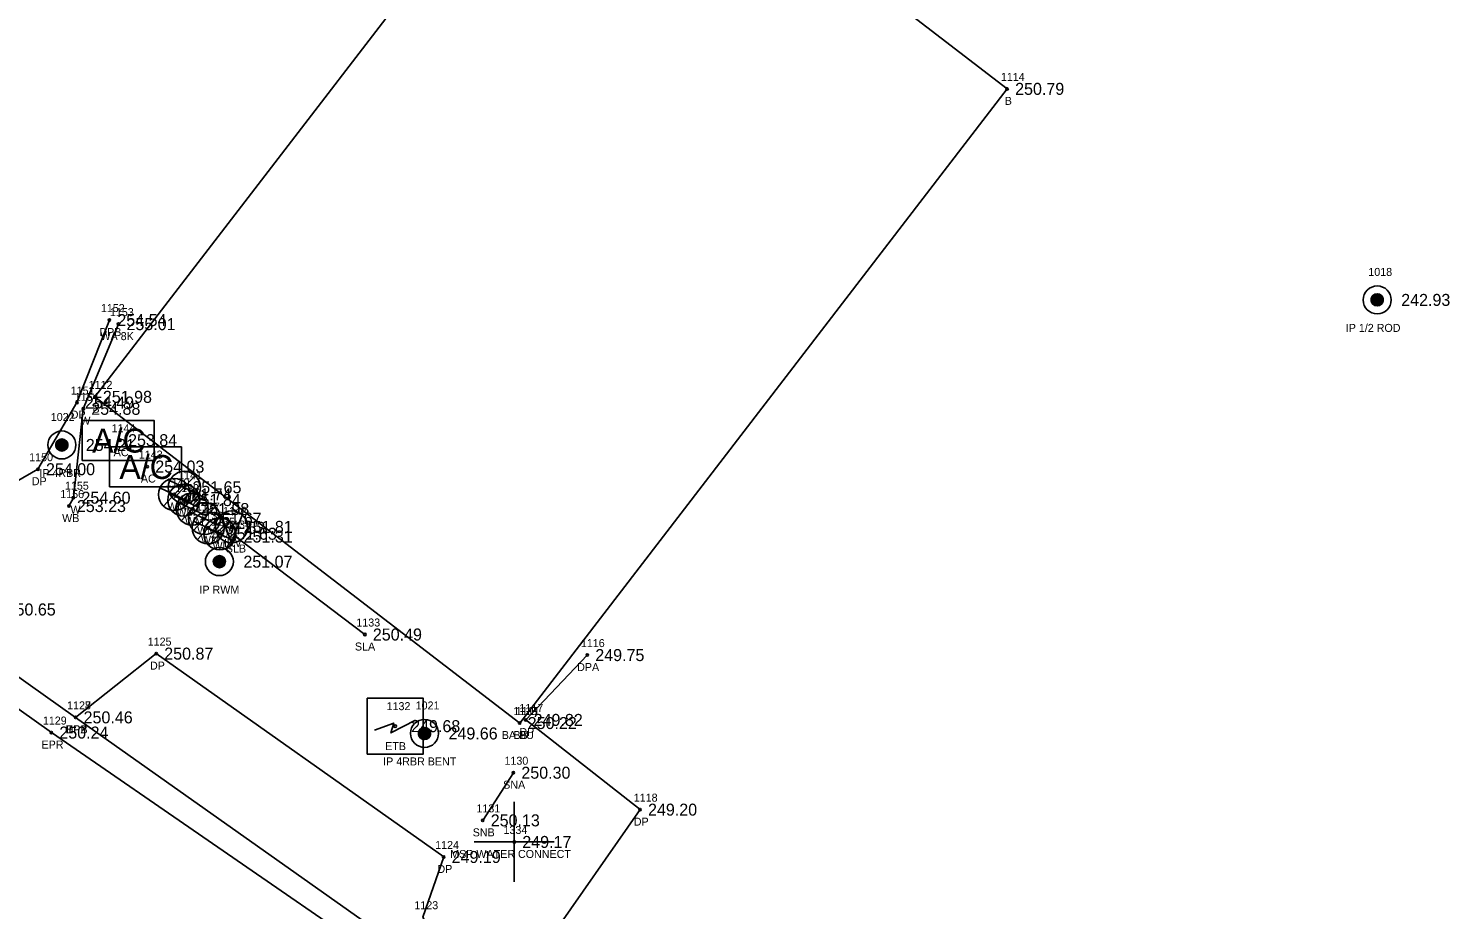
# Model space of a CAD drawing. Extents: x 1961231 to 1962574, y 799865 to 801120.
# Drawn here: x 1962101.5 to 1962279.1, y 800461.9 to 800572.1 of the extents above; entities that cross this region are included whole.
import ezdxf

# ---------------------------------------------------------------- set-up
doc = ezdxf.new("R2010")
doc.units = 0
for name, color, linetype in [('RD_EX_Bldg', 7, 'Continuous'), ('RD_EX_Bldg_txCode', 7, 'Continuous'), ('RD_EX_BldgApp', 7, 'Continuous'), ('RD_EX_BldgApp_txCode', 7, 'Continuous'), ('RD_EX_Driveway', 7, 'Continuous'), ('RD_EX_Driveway_txCode', 7, 'Continuous'), ('RD_EX_DV_Prop_txCode', 7, 'Continuous'), ('RD_EX_DV_PropPin', 7, 'Continuous'), ('RD_EX_Misc', 7, 'Continuous'), ('RD_EX_Misc_txCode', 7, 'Continuous'), ('RD_EX_Road', 7, 'Continuous'), ('RD_EX_Road_txCode', 7, 'Continuous'), ('RD_EX_TX_Bldg_ELEV', 7, 'Continuous'), ('RD_EX_TX_BldgApp_ELEV', 7, 'Continuous'), ('RD_EX_TX_Driveway_ELEV', 7, 'Continuous'), ('RD_EX_TX_DV_Prop_ELEV', 7, 'Continuous'), ('RD_EX_TX_Misc_ELEV', 7, 'Continuous'), ('RD_EX_TX_Road_ELEV', 7, 'Continuous'), ('RD_EX_TX_UT_ELEV', 7, 'Continuous'), ('RD_EX_TX_VEG_ELEV', 7, 'Continuous'), ('RD_EX_UT', 7, 'Continuous'), ('RD_EX_UT_txCode', 7, 'Continuous'), ('RD_EX_VEG', 7, 'Continuous'), ('RD_EX_VEG_txCode', 7, 'Continuous'), ('RD_SMD_Locator', 7, 'Continuous')]:
    doc.layers.add(name, color=color, linetype=linetype)

msp = doc.modelspace()

# ---------------------------------------------------------------- linework, layer by layer
at = {"layer": 'RD_EX_Bldg'}
msp.add_lwpolyline([(1962162.93, 800485.25), (1962109.84, 800526.04), (1962170.76, 800605.34), (1962223.85, 800564.55), (1962162.93, 800485.25)], dxfattribs=at)
at = {"layer": 'RD_EX_BldgApp'}
for p, q in [((1962126.93, 800507.79), (1962125.63, 800511.27)), ((1962126.93, 800507.79), (1962128.26, 800511.24)), ((1962162.14, 800479.04), (1962158.31, 800473.08))]:
    msp.add_line(p, q, dxfattribs=at)
msp.add_lwpolyline([(1962112.79, 800535.13), (1962108.39, 800524.54), (1962107.16, 800513.43), (1962106.59, 800512.38)], dxfattribs=at)
for points in [[(1962108.25, 800518.06), (1962108.25, 800523.06), (1962117.25, 800523.06), (1962117.25, 800518.06)], [(1962111.65, 800514.77), (1962111.65, 800519.77), (1962120.65, 800519.77), (1962120.65, 800514.77)]]:
    msp.add_lwpolyline(points, close=True, dxfattribs=at)
for radius in [2, 0.15]:
    msp.add_circle((1962126.93, 800509.78), radius, dxfattribs=at)
at = {"layer": 'RD_EX_Driveway'}
for points in [[(1962091.52, 800497.24), (1962089.57, 800504.73), (1962092.49, 800511.12), (1962102.73, 800516.99), (1962107.6, 800525.32), (1962111.65, 800535.64)], [(1962171.38, 800493.75), (1962163.68, 800485.64), (1962177.97, 800474.42), (1962166.53, 800458.03), (1962152.89, 800453.77), (1962153.39, 800455.94), (1962150.83, 800460.97), (1962153.43, 800468.5), (1962117.51, 800493.93), (1962107.43, 800485.96)]]:
    msp.add_lwpolyline(points, dxfattribs=at)
at = {"layer": 'RD_EX_DV_PropPin'}
for p, q in [((1962269.36, 800537.97), (1962269.36, 800538.36)), ((1962269.4, 800537.86), (1962269.4, 800538.46)), ((1962269.43, 800537.79), (1962269.43, 800538.53)), ((1962269.47, 800537.74), (1962269.47, 800538.59)), ((1962269.5, 800537.69), (1962269.5, 800538.64)), ((1962269.54, 800537.65), (1962269.54, 800538.68)), ((1962269.57, 800537.61), (1962269.57, 800538.71)), ((1962269.61, 800537.58), (1962269.61, 800538.75)), ((1962269.64, 800537.55), (1962269.64, 800538.77)), ((1962269.68, 800537.53), (1962269.68, 800538.8)), ((1962269.71, 800537.51), (1962269.71, 800538.82)), ((1962269.75, 800537.49), (1962269.75, 800538.84)), ((1962269.78, 800537.47), (1962269.78, 800538.86)), ((1962269.82, 800537.46), (1962269.82, 800538.87)), ((1962269.85, 800537.44), (1962269.85, 800538.88)), ((1962269.89, 800537.43), (1962269.89, 800538.89)), ((1962269.92, 800537.42), (1962269.92, 800538.9)), ((1962269.96, 800537.41), (1962269.96, 800538.91)), ((1962269.99, 800537.41), (1962269.99, 800538.92)), ((1962270.03, 800537.41), (1962270.03, 800538.92)), ((1962270.06, 800537.4), (1962270.06, 800538.92)), ((1962270.1, 800537.4), (1962270.1, 800538.92)), ((1962270.13, 800537.4), (1962270.13, 800538.92)), ((1962270.17, 800537.41), (1962270.17, 800538.92)), ((1962270.2, 800537.41), (1962270.2, 800538.92)), ((1962270.24, 800537.41), (1962270.24, 800538.91)), ((1962270.27, 800537.42), (1962270.27, 800538.9)), ((1962270.31, 800537.43), (1962270.31, 800538.89)), ((1962270.34, 800537.44), (1962270.34, 800538.88)), ((1962270.38, 800537.46), (1962270.38, 800538.87)), ((1962270.41, 800537.47), (1962270.41, 800538.86)), ((1962270.45, 800537.49), (1962270.45, 800538.84)), ((1962270.48, 800537.51), (1962270.48, 800538.82)), ((1962270.52, 800537.53), (1962270.52, 800538.8)), ((1962270.55, 800537.55), (1962270.55, 800538.77)), ((1962270.59, 800537.58), (1962270.59, 800538.75)), ((1962270.62, 800537.61), (1962270.62, 800538.71)), ((1962270.66, 800537.65), (1962270.66, 800538.68)), ((1962270.69, 800537.69), (1962270.69, 800538.64)), ((1962270.73, 800537.74), (1962270.73, 800538.59)), ((1962270.76, 800537.79), (1962270.76, 800538.53)), ((1962270.8, 800537.86), (1962270.8, 800538.46)), ((1962270.83, 800537.97), (1962270.83, 800538.36)), ((1962104.98, 800519.82), (1962104.98, 800520.21)), ((1962105.01, 800519.72), (1962105.01, 800520.31)), ((1962105.05, 800519.65), (1962105.05, 800520.39)), ((1962105.08, 800519.59), (1962105.08, 800520.44)), ((1962105.12, 800519.54), (1962105.12, 800520.49)), ((1962105.15, 800519.5), (1962105.15, 800520.53)), ((1962105.19, 800519.47), (1962105.19, 800520.57)), ((1962105.22, 800519.43), (1962105.22, 800520.6)), ((1962105.26, 800519.41), (1962105.26, 800520.63)), ((1962105.29, 800519.38), (1962105.29, 800520.65)), ((1962105.33, 800519.36), (1962105.33, 800520.67)), ((1962105.36, 800519.34), (1962105.36, 800520.69)), ((1962105.4, 800519.32), (1962105.4, 800520.71)), ((1962105.43, 800519.31), (1962105.43, 800520.72)), ((1962105.47, 800519.3), (1962105.47, 800520.74)), ((1962105.5, 800519.28), (1962105.5, 800520.75)), ((1962105.54, 800519.28), (1962105.54, 800520.76)), ((1962105.57, 800519.27), (1962105.57, 800520.76)), ((1962105.61, 800519.26), (1962105.61, 800520.77)), ((1962105.64, 800519.26), (1962105.64, 800520.77)), ((1962105.68, 800519.26), (1962105.68, 800520.78)), ((1962105.71, 800519.25), (1962105.71, 800520.78)), ((1962105.75, 800519.26), (1962105.75, 800520.78)), ((1962105.78, 800519.26), (1962105.78, 800520.77)), ((1962105.82, 800519.26), (1962105.82, 800520.77)), ((1962105.85, 800519.27), (1962105.85, 800520.76)), ((1962105.89, 800519.28), (1962105.89, 800520.76)), ((1962105.92, 800519.28), (1962105.92, 800520.75)), ((1962105.96, 800519.3), (1962105.96, 800520.74)), ((1962105.99, 800519.31), (1962105.99, 800520.72)), ((1962106.03, 800519.32), (1962106.03, 800520.71)), ((1962106.06, 800519.34), (1962106.06, 800520.69)), ((1962106.1, 800519.36), (1962106.1, 800520.67)), ((1962106.13, 800519.38), (1962106.13, 800520.65)), ((1962106.17, 800519.41), (1962106.17, 800520.63)), ((1962106.2, 800519.43), (1962106.2, 800520.6)), ((1962106.24, 800519.47), (1962106.24, 800520.57)), ((1962106.27, 800519.5), (1962106.27, 800520.53)), ((1962106.31, 800519.54), (1962106.31, 800520.49)), ((1962106.34, 800519.59), (1962106.34, 800520.44)), ((1962106.38, 800519.65), (1962106.38, 800520.39)), ((1962106.41, 800519.72), (1962106.41, 800520.31)), ((1962106.45, 800519.82), (1962106.45, 800520.21)), ((1962124.66, 800505.24), (1962124.66, 800505.63)), ((1962124.7, 800505.14), (1962124.7, 800505.73)), ((1962124.73, 800505.06), (1962124.73, 800505.8)), ((1962124.77, 800505.01), (1962124.77, 800505.86)), ((1962124.8, 800504.96), (1962124.8, 800505.91)), ((1962124.84, 800504.92), (1962124.84, 800505.95)), ((1962124.87, 800504.88), (1962124.87, 800505.98)), ((1962124.91, 800504.85), (1962124.91, 800506.02)), ((1962124.94, 800504.82), (1962124.94, 800506.04)), ((1962124.98, 800504.8), (1962124.98, 800506.07)), ((1962125.01, 800504.78), (1962125.01, 800506.09)), ((1962125.05, 800504.76), (1962125.05, 800506.11)), ((1962125.08, 800504.74), (1962125.08, 800506.13)), ((1962125.12, 800504.73), (1962125.12, 800506.14)), ((1962125.15, 800504.71), (1962125.15, 800506.15)), ((1962125.19, 800504.7), (1962125.19, 800506.16)), ((1962125.22, 800504.69), (1962125.22, 800506.17)), ((1962125.26, 800504.69), (1962125.26, 800506.18)), ((1962125.29, 800504.68), (1962125.29, 800506.19)), ((1962125.33, 800504.68), (1962125.33, 800506.19)), ((1962125.36, 800504.67), (1962125.36, 800506.19)), ((1962125.4, 800504.67), (1962125.4, 800506.19)), ((1962125.43, 800504.67), (1962125.43, 800506.19)), ((1962125.47, 800504.68), (1962125.47, 800506.19)), ((1962125.5, 800504.68), (1962125.5, 800506.19)), ((1962125.54, 800504.69), (1962125.54, 800506.18)), ((1962125.57, 800504.69), (1962125.57, 800506.17)), ((1962125.61, 800504.7), (1962125.61, 800506.16)), ((1962125.64, 800504.71), (1962125.64, 800506.15)), ((1962125.68, 800504.73), (1962125.68, 800506.14)), ((1962125.71, 800504.74), (1962125.71, 800506.13)), ((1962125.75, 800504.76), (1962125.75, 800506.11)), ((1962125.78, 800504.78), (1962125.78, 800506.09)), ((1962125.82, 800504.8), (1962125.82, 800506.07)), ((1962125.85, 800504.82), (1962125.85, 800506.04)), ((1962125.89, 800504.85), (1962125.89, 800506.02)), ((1962125.92, 800504.88), (1962125.92, 800505.98)), ((1962125.96, 800504.92), (1962125.96, 800505.95)), ((1962125.99, 800504.96), (1962125.99, 800505.91)), ((1962126.03, 800505.01), (1962126.03, 800505.86)), ((1962126.06, 800505.06), (1962126.06, 800505.8)), ((1962126.1, 800505.14), (1962126.1, 800505.73)), ((1962126.13, 800505.24), (1962126.13, 800505.63)), ((1962150.37, 800483.58), (1962150.37, 800484.32)), ((1962150.41, 800483.52), (1962150.41, 800484.37)), ((1962150.44, 800483.47), (1962150.44, 800484.42)), ((1962150.48, 800483.43), (1962150.48, 800484.46)), ((1962150.51, 800483.4), (1962150.51, 800484.5)), ((1962150.55, 800483.37), (1962150.55, 800484.53)), ((1962150.58, 800483.34), (1962150.58, 800484.56)), ((1962150.62, 800483.31), (1962150.62, 800484.58)), ((1962150.65, 800483.29), (1962150.65, 800484.6)), ((1962150.69, 800483.27), (1962150.69, 800484.62)), ((1962150.72, 800483.25), (1962150.72, 800484.64)), ((1962150.76, 800483.24), (1962150.76, 800484.66)), ((1962150.79, 800483.23), (1962150.79, 800484.67)), ((1962150.83, 800483.22), (1962150.83, 800484.68)), ((1962150.86, 800483.21), (1962150.86, 800484.69)), ((1962150.9, 800483.2), (1962150.9, 800484.7)), ((1962150.93, 800483.19), (1962150.93, 800484.7)), ((1962150.97, 800483.19), (1962150.97, 800484.71)), ((1962151, 800483.19), (1962151, 800484.71)), ((1962151.04, 800483.19), (1962151.04, 800484.71)), ((1962151.07, 800483.19), (1962151.07, 800484.71)), ((1962151.11, 800483.19), (1962151.11, 800484.71)), ((1962151.14, 800483.19), (1962151.14, 800484.7)), ((1962151.18, 800483.2), (1962151.18, 800484.7)), ((1962151.21, 800483.21), (1962151.21, 800484.69)), ((1962151.25, 800483.22), (1962151.25, 800484.68)), ((1962151.28, 800483.23), (1962151.28, 800484.67)), ((1962151.32, 800483.24), (1962151.32, 800484.66)), ((1962151.35, 800483.25), (1962151.35, 800484.64)), ((1962151.39, 800483.27), (1962151.39, 800484.62)), ((1962151.42, 800483.29), (1962151.42, 800484.6)), ((1962151.46, 800483.31), (1962151.46, 800484.58)), ((1962151.49, 800483.34), (1962151.49, 800484.56)), ((1962151.53, 800483.37), (1962151.53, 800484.53)), ((1962151.56, 800483.4), (1962151.56, 800484.5)), ((1962151.6, 800483.43), (1962151.6, 800484.46)), ((1962151.63, 800483.47), (1962151.63, 800484.42)), ((1962151.67, 800483.52), (1962151.67, 800484.37)), ((1962151.7, 800483.58), (1962151.7, 800484.32)), ((1962150.3, 800483.75), (1962150.3, 800484.14)), ((1962150.34, 800483.65), (1962150.34, 800484.25)), ((1962151.74, 800483.65), (1962151.74, 800484.25)), ((1962151.77, 800483.75), (1962151.77, 800484.14))]:
    msp.add_line(p, q, dxfattribs=at)
for centre, radius in [((1962270.1, 800538.16), 1.75), ((1962270.1, 800538.16), 0.761), ((1962105.71, 800520.02), 1.75), ((1962105.71, 800520.02), 0.761), ((1962125.4, 800505.43), 1.75), ((1962125.4, 800505.43), 0.761), ((1962151.04, 800483.95), 1.75), ((1962151.04, 800483.95), 0.761)]:
    msp.add_circle(centre, radius, dxfattribs=at)
at = {"layer": 'RD_EX_Misc'}
for p, q in [((1962162.26, 800465.38), (1962162.26, 800475.38)), ((1962157.26, 800470.38), (1962167.26, 800470.38))]:
    msp.add_line(p, q, dxfattribs=at)
at = {"layer": 'RD_EX_Road'}
for points in [[(1962276.74, 800366.53), (1962275.76, 800367.28), (1962226.46, 800400.66), (1962183.05, 800429.73), (1962145.98, 800455.38), (1962104.4, 800484.06), (1962056.77, 800517.94), (1962023.95, 800541.05), (1961991.87, 800563.56), (1961983.89, 800569.94), (1961938.77, 800603.67), (1961913.43, 800623.83), (1961897.73, 800636.17), (1961851.62, 800671.61), (1961815.86, 800699.48), (1961795.77, 800715.49), (1961771.88, 800733.73), (1961750.77, 800750.96), (1961735.63, 800762.82), (1961702.92, 800788.52)], [(1962275.76, 800367.28), (1962274.03, 800371.18), (1962275.17, 800373.82), (1962239.93, 800394.94), (1962227.76, 800403.12), (1962207.73, 800416.44), (1962184.45, 800431.68), (1962152.89, 800453.77), (1962107.43, 800485.96), (1962091.52, 800497.24), (1962058.28, 800520.2), (1962027.14, 800543.26), (1961995.14, 800564.69), (1961983.89, 800569.94)]]:
    msp.add_lwpolyline(points, dxfattribs=at)
at = {"layer": 'RD_EX_UT'}
for p, q in [((1962117.94, 800514.66), (1962121.57, 800512.95)), ((1962118.43, 800512.37), (1962121.09, 800515.26)), ((1962119.18, 800515.57), (1962122.81, 800513.85)), ((1962119.59, 800511.67), (1962122.26, 800514.57)), ((1962119.67, 800513.27), (1962122.33, 800516.17)), ((1962119.11, 800513.97), (1962122.74, 800512.25)), ((1962120.17, 800512.85), (1962123.8, 800511.14)), ((1962120.65, 800510.56), (1962123.31, 800513.45)), ((1962121.71, 800511.66), (1962125.34, 800509.95)), ((1962122.19, 800509.37), (1962124.85, 800512.26)), ((1962122.65, 800508.2), (1962125.32, 800511.09)), ((1962122.17, 800510.49), (1962125.8, 800508.78)), ((1962123.61, 800509.76), (1962127.24, 800508.04)), ((1962124.09, 800507.46), (1962126.76, 800510.36))]:
    msp.add_line(p, q, dxfattribs=at)
msp.add_lwpolyline([(1962143.87, 800481.36), (1962143.87, 800488.36), (1962150.87, 800488.36), (1962150.87, 800481.36)], close=True, dxfattribs=at)
msp.add_lwpolyline([(1962144.77, 800484.35), (1962147.19, 800485.25), (1962146.84, 800484.01), (1962149.89, 800485.6)], dxfattribs=at)
for centre in [(1962121.02, 800514.73), (1962119.78, 800513.83), (1962120.94, 800513.13), (1962122, 800512.01), (1962123.54, 800510.82), (1962124, 800509.66), (1962125.44, 800508.92)]:
    msp.add_circle(centre, 2, dxfattribs=at)
at = {"layer": 'RD_EX_VEG'}
msp.add_line((1962143.58, 800496.32), (1962127.43, 800508.57), dxfattribs=at)
at = {"layer": 'RD_SMD_Locator'}
for centre in [(1962223.85, 800564.55), (1962270.1, 800538.16), (1962111.65, 800535.64), (1962112.79, 800535.13), (1962107.6, 800525.32), (1962109.84, 800526.04), (1962108.39, 800524.54), (1962105.71, 800520.02), (1962112.99, 800520.62), (1962102.73, 800516.99), (1962116.39, 800517.32), (1962121.02, 800514.73), (1962107.16, 800513.43), (1962119.78, 800513.83), (1962120.94, 800513.13), (1962106.59, 800512.38), (1962122, 800512.01), (1962123.54, 800510.82), (1962124, 800509.66), (1962125.44, 800508.92), (1962127.43, 800508.57), (1962125.4, 800505.43), (1962143.58, 800496.32), (1962117.51, 800493.93), (1962171.38, 800493.75), (1962107.43, 800485.96), (1962107.43, 800485.96), (1962147.37, 800484.86), (1962162.93, 800485.25), (1962162.93, 800485.25), (1962163.68, 800485.64), (1962104.4, 800484.06), (1962151.04, 800483.95), (1962162.14, 800479.04), (1962177.97, 800474.42), (1962158.31, 800473.08), (1962162.26, 800470.38), (1962153.43, 800468.5)]:
    msp.add_circle(centre, 0.15, dxfattribs=at)

# ---------------------------------------------------------------- texts
at = {"layer": 'RD_EX_Bldg_txCode'}
for s, p in [('1114', (1962223.07, 800565.55)), ('B', (1962223.55, 800562.55)), ('1112', (1962109.06, 800527.04)), ('B', (1962109.53, 800524.04)), ('1115', (1962162.15, 800486.25)), ('1111', (1962162.43, 800486.25)), ('BA BU', (1962160.69, 800483.25)), ('BB', (1962162.15, 800483.25))]:
    msp.add_text(s, height=1, dxfattribs=at).set_placement(p)
at = {"layer": 'RD_EX_BldgApp'}
for p in [(1962109.5, 800519.07), (1962112.9, 800515.77)]:
    msp.add_text('A/C', height=3, dxfattribs=at).set_placement(p)
at = {"layer": 'RD_EX_BldgApp_txCode'}
for s, p in [('1144', (1962111.93, 800521.62)), ('AC', (1962112.19, 800518.62)), ('1143', (1962115.33, 800518.32)), ('AC', (1962115.59, 800515.32)), ('1130', (1962161.03, 800480.04)), ('SNA', (1962160.87, 800477.04)), ('1131', (1962157.53, 800474.08)), ('SNB', (1962157.06, 800471.08))]:
    msp.add_text(s, height=1, dxfattribs=at).set_placement(p)
at = {"layer": 'RD_EX_Driveway_txCode'}
for s, p in [('1152', (1962110.59, 800536.64)), ('DPB', (1962110.4, 800533.64)), ('1151', (1962106.82, 800526.32)), ('DP', (1962106.82, 800523.32)), ('1150', (1962101.63, 800517.99)), ('DP', (1962101.96, 800514.99)), ('1125', (1962116.44, 800494.93)), ('1116', (1962170.58, 800494.75)), ('DP', (1962116.73, 800491.93)), ('DPA', (1962170.11, 800491.75)), ('1127', (1962106.37, 800486.96)), ('1117', (1962162.9, 800486.64)), ('DPB', (1962106.18, 800483.96)), ('DP', (1962162.9, 800483.64)), ('1118', (1962177.19, 800475.42)), ('DP', (1962177.19, 800472.42)), ('1124', (1962152.37, 800469.5)), ('DP', (1962152.65, 800466.5)), ('1123', (1962149.77, 800461.97))]:
    msp.add_text(s, height=1, dxfattribs=at).set_placement(p)
at = {"layer": 'RD_EX_DV_Prop_txCode'}
for s, p in [('1018', (1962268.99, 800541.16)), ('IP 1/2 ROD', (1962266.17, 800534.16)), ('1022', (1962104.33, 800523.02)), ('IP 4RBR', (1962102.9, 800516.02)), ('1001', (1962124.25, 800508.43)), ('IP RWM', (1962122.91, 800501.43)), ('1021', (1962149.93, 800486.95)), ('IP 4RBR BENT', (1962145.87, 800479.95))]:
    msp.add_text(s, height=1, dxfattribs=at).set_placement(p)
at = {"layer": 'RD_EX_Misc_txCode'}
for s, p in [('1153', (1962111.72, 800536.13)), ('WA 8K', (1962110.54, 800533.13)), ('1154', (1962107.33, 800525.54)), ('W', (1962108.02, 800522.54)), ('1155', (1962106.1, 800514.43)), ('1156', (1962105.51, 800513.38)), ('WB', (1962105.75, 800510.38)), ('W', (1962106.79, 800511.43)), ('1142', (1962125.87, 800511.28)), ('IRV', (1962125.97, 800507.28)), ('1334', (1962160.91, 800471.38)), ('MSP WATER CONNECT', (1962154.25, 800468.38))]:
    msp.add_text(s, height=1, dxfattribs=at).set_placement(p)
at = {"layer": 'RD_EX_Road_txCode'}
for s, p in [('1128', (1962106.37, 800486.96)), ('1129', (1962103.34, 800485.06)), ('EP2', (1962106.23, 800483.96)), ('EPR', (1962103.17, 800482.06))]:
    msp.add_text(s, height=1, dxfattribs=at).set_placement(p)
at = {"layer": 'RD_EX_TX_Bldg_ELEV'}
for s, p in [('250.79', (1962224.85, 800563.8)), ('251.98', (1962110.84, 800525.29)), ('250.22', (1962163.93, 800484.5)), ('250.22', (1962163.93, 800484.5))]:
    msp.add_text(s, height=1.5, dxfattribs=at).set_placement(p)
at = {"layer": 'RD_EX_TX_BldgApp_ELEV'}
for s, p in [('253.84', (1962113.99, 800519.87)), ('254.03', (1962117.39, 800516.57)), ('250.30', (1962163.14, 800478.29)), ('250.13', (1962159.31, 800472.33))]:
    msp.add_text(s, height=1.5, dxfattribs=at).set_placement(p)
at = {"layer": 'RD_EX_TX_Driveway_ELEV'}
for s, p in [('254.54', (1962112.65, 800534.89)), ('254.49', (1962108.6, 800524.57)), ('254.00', (1962103.73, 800516.24)), ('250.87', (1962118.51, 800493.18)), ('249.75', (1962172.38, 800493)), ('250.46', (1962108.43, 800485.21)), ('249.82', (1962164.68, 800484.89)), ('249.20', (1962178.97, 800473.67)), ('249.19', (1962154.43, 800467.75))]:
    msp.add_text(s, height=1.5, dxfattribs=at).set_placement(p)
at = {"layer": 'RD_EX_TX_DV_Prop_ELEV'}
for s, p in [('242.93', (1962273.1, 800537.41)), ('254.21', (1962108.71, 800519.27)), ('251.07', (1962128.4, 800504.68)), ('249.66', (1962154.04, 800483.2))]:
    msp.add_text(s, height=1.5, dxfattribs=at).set_placement(p)
at = {"layer": 'RD_EX_TX_Misc_ELEV'}
for s, p in [('255.01', (1962113.79, 800534.38)), ('254.88', (1962109.39, 800523.79)), ('253.23', (1962107.59, 800511.63)), ('254.60', (1962108.16, 800512.68)), ('251.81', (1962128.43, 800509.03)), ('249.17', (1962163.26, 800469.63))]:
    msp.add_text(s, height=1.5, dxfattribs=at).set_placement(p)
at = {"layer": 'RD_EX_TX_Road_ELEV'}
for s, p in [('250.46', (1962108.43, 800485.21)), ('250.24', (1962105.4, 800483.31))]:
    msp.add_text(s, height=1.5, dxfattribs=at).set_placement(p)
at = {"layer": 'RD_EX_TX_UT_ELEV'}
for s, p in [('251.74', (1962120.78, 800513.08)), ('251.65', (1962122.02, 800513.98)), ('251.84', (1962121.94, 800512.38)), ('251.98', (1962123, 800511.26)), ('251.67', (1962124.54, 800510.07)), ('251.53', (1962125, 800508.91)), ('251.63', (1962126.44, 800508.17)), ('250.65', (1962098.81, 800498.7)), ('249.68', (1962149.37, 800484.11))]:
    msp.add_text(s, height=1.5, dxfattribs=at).set_placement(p)
at = {"layer": 'RD_EX_TX_VEG_ELEV'}
for s, p in [('251.31', (1962128.43, 800507.82)), ('250.49', (1962144.58, 800495.57))]:
    msp.add_text(s, height=1.5, dxfattribs=at).set_placement(p)
at = {"layer": 'RD_EX_UT_txCode'}
for s, p in [('1141', (1962120.24, 800515.73)), ('1140', (1962118.68, 800514.83)), ('1139', (1962119.88, 800514.13)), ('WM', (1962118.87, 800511.83)), ('WM', (1962120.11, 800512.73)), ('1138', (1962120.94, 800513.01)), ('1137', (1962122.48, 800511.82)), ('WM', (1962120.04, 800511.13)), ('WM', (1962121.09, 800510.01)), ('1136', (1962122.92, 800510.66)), ('1135', (1962124.38, 800509.92)), ('WM', (1962122.63, 800508.82)), ('WM', (1962123.1, 800507.66)), ('WM', (1962124.54, 800506.92)), ('1132', (1962146.3, 800486.86)), ('ETB', (1962146.12, 800481.86))]:
    msp.add_text(s, height=1, dxfattribs=at).set_placement(p)
at = {"layer": 'RD_EX_VEG_txCode'}
for s, p in [('1134', (1962126.37, 800509.57)), ('SLB', (1962126.21, 800506.57)), ('1133', (1962142.52, 800497.32)), ('SLA', (1962142.34, 800494.32))]:
    msp.add_text(s, height=1, dxfattribs=at).set_placement(p)

doc.saveas('drawing.dxf')
